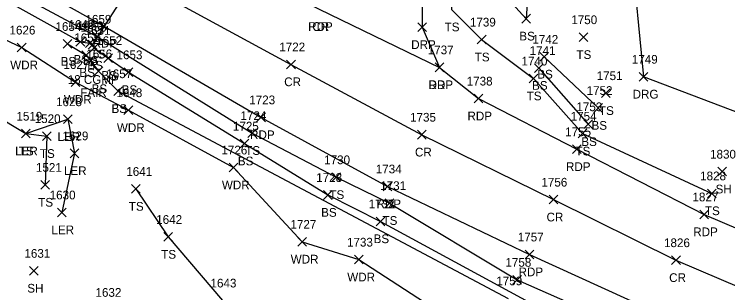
# Model space of a CAD drawing. Extents: x 1586965 to 1590952, y 716317 to 720029.
# Drawn here: x 1587975.1 to 1588139.1, y 719679.3 to 719743.2 of the extents above; entities that cross this region are included whole.
import ezdxf

# ---------------------------------------------------------------- set-up
doc = ezdxf.new("R2010")
doc.units = 0
for name, color, linetype in [('D_A', 7, 'Continuous'), ('D_C', 7, 'Continuous'), ('D_I', 7, 'Continuous'), ('D_TIC', 7, 'Continuous'), ('DCP', 7, 'Continuous'), ('L_A', 7, 'Continuous'), ('L_I', 7, 'Continuous'), ('L_TIC', 7, 'Continuous'), ('LARO', 7, 'Continuous'), ('LAWA', 7, 'Continuous'), ('LELB', 7, 'Continuous'), ('P_A', 7, 'Continuous'), ('P_I', 7, 'Continuous'), ('P_TIC', 7, 'Continuous'), ('PET', 7, 'Continuous'), ('PRC', 7, 'Continuous'), ('R_A', 7, 'Continuous'), ('R_I', 7, 'Continuous'), ('R_TIC', 7, 'Continuous'), ('RDG', 7, 'Continuous'), ('RDP', 7, 'Continuous')]:
    doc.layers.add(name, color=color, linetype=linetype)

msp = doc.modelspace()

# ---------------------------------------------------------------- linework, layer by layer
at = {"layer": 'D_TIC'}
for points in [[(1587992.11, 719735.22), (1587994.11, 719737.22)], [(1587994.11, 719735.22), (1587992.11, 719737.22)]]:
    msp.add_lwpolyline(points, dxfattribs=at)
at = {"layer": 'DCP'}
msp.add_lwpolyline([(1587993.11, 719736.22), (1588025.22, 719785.95)], dxfattribs=at)
at = {"layer": 'L_TIC'}
for points in [[(1588091.75, 719741.19), (1588093.75, 719743.19)], [(1588093.75, 719741.19), (1588091.75, 719743.19)], [(1587993.24, 719737.05), (1587995.24, 719739.05)], [(1587995.24, 719737.05), (1587993.24, 719739.05)], [(1588104.92, 719736.94), (1588106.92, 719738.94)], [(1588106.92, 719736.94), (1588104.92, 719738.94)], [(1587986.33, 719735.39), (1587988.33, 719737.39)], [(1587988.33, 719735.39), (1587986.33, 719737.39)], [(1587989.31, 719735.86), (1587991.31, 719737.86)], [(1587991.31, 719735.86), (1587989.31, 719737.86)], [(1587991.49, 719735.59), (1587993.49, 719737.59)], [(1587993.49, 719735.59), (1587991.49, 719737.59)], [(1588081.54, 719736.39), (1588083.54, 719738.39)], [(1588083.54, 719736.39), (1588081.54, 719738.39)], [(1587975.83, 719734.56), (1587977.83, 719736.56)], [(1587977.83, 719734.56), (1587975.83, 719736.56)], [(1587992.47, 719734.49), (1587994.47, 719736.49)], [(1587994.47, 719734.49), (1587992.47, 719736.49)], [(1587990.65, 719732.83), (1587992.65, 719734.83)], [(1587992.65, 719732.83), (1587990.65, 719734.83)], [(1587995.7, 719732.15), (1587997.7, 719734.15)], [(1587997.7, 719732.15), (1587995.7, 719734.15)], [(1588095.88, 719732.44), (1588097.88, 719734.44)], [(1588097.88, 719732.44), (1588095.88, 719734.44)], [(1587993.47, 719729.11), (1587995.47, 719731.11)], [(1587995.47, 719729.11), (1587993.47, 719731.11)], [(1588000.37, 719728.89), (1588002.37, 719730.89)], [(1588002.37, 719728.89), (1588000.37, 719730.89)], [(1588094.69, 719729.86), (1588096.69, 719731.86)], [(1588096.69, 719729.86), (1588094.69, 719731.86)], [(1588093.48, 719727.45), (1588095.48, 719729.45)], [(1588095.48, 719727.45), (1588093.48, 719729.45)], [(1587988.17, 719726.65), (1587990.17, 719728.65)], [(1587990.17, 719726.65), (1587988.17, 719728.65)], [(1587998.02, 719724.54), (1588000.02, 719726.54)], [(1588000.02, 719724.54), (1587998.02, 719726.54)], [(1588110.09, 719724.09), (1588112.09, 719726.09)], [(1588112.09, 719724.09), (1588110.09, 719726.09)], [(1588108.35, 719720.69), (1588110.35, 719722.69)], [(1588110.35, 719720.69), (1588108.35, 719722.69)], [(1588000.34, 719720.18), (1588002.34, 719722.18)], [(1588002.34, 719720.18), (1588000.34, 719722.18)], [(1587986.47, 719718.11), (1587988.47, 719720.11)], [(1587988.47, 719718.11), (1587986.47, 719720.11)], [(1588106.01, 719716.96), (1588108.01, 719718.96)], [(1588108.01, 719716.96), (1588106.01, 719718.96)], [(1587976.76, 719714.8), (1587978.76, 719716.8)], [(1587978.76, 719714.8), (1587976.76, 719716.8)], [(1587976.76, 719714.8), (1587978.76, 719716.8)], [(1587978.76, 719714.8), (1587976.76, 719716.8)], [(1587981.6, 719714.23), (1587983.6, 719716.23)], [(1587983.6, 719714.23), (1587981.6, 719716.23)], [(1588028.81, 719714.93), (1588030.81, 719716.93)], [(1588030.81, 719714.93), (1588028.81, 719716.93)], [(1588104.69, 719714.8), (1588106.69, 719716.8)], [(1588106.69, 719714.8), (1588104.69, 719716.8)], [(1588027.07, 719712.52), (1588029.07, 719714.52)], [(1588029.07, 719712.52), (1588027.07, 719714.52)], [(1587987.96, 719710.28), (1587989.96, 719712.28)], [(1587989.96, 719710.28), (1587987.96, 719712.28)], [(1588024.48, 719707.03), (1588026.48, 719709.03)], [(1588026.48, 719707.03), (1588024.48, 719709.03)], [(1588136.81, 719706.08), (1588138.81, 719708.08)], [(1588138.81, 719706.08), (1588136.81, 719708.08)], [(1588048.13, 719704.79), (1588050.13, 719706.79)], [(1588050.13, 719704.79), (1588048.13, 719706.79)], [(1587981.22, 719703.04), (1587983.22, 719705.04)], [(1587983.22, 719703.04), (1587981.22, 719705.04)], [(1588002.04, 719702.11), (1588004.04, 719704.11)], [(1588004.04, 719702.11), (1588002.04, 719704.11)], [(1588046.21, 719700.72), (1588048.21, 719702.72)], [(1588048.21, 719700.72), (1588046.21, 719702.72)], [(1588134.44, 719701.09), (1588136.44, 719703.09)], [(1588136.44, 719701.09), (1588134.44, 719703.09)], [(1588060.35, 719698.86), (1588062.35, 719700.86)], [(1588062.35, 719698.86), (1588060.35, 719700.86)], [(1587985.09, 719696.71), (1587987.09, 719698.71)], [(1587987.09, 719696.71), (1587985.09, 719698.71)], [(1588058.27, 719694.66), (1588060.27, 719696.66)], [(1588060.27, 719694.66), (1588058.27, 719696.66)], [(1588009.49, 719691.09), (1588011.49, 719693.09)], [(1588011.49, 719691.09), (1588009.49, 719693.09)], [(1588040.3, 719689.98), (1588042.3, 719691.98)], [(1588042.3, 719689.98), (1588040.3, 719691.98)], [(1588053.29, 719685.88), (1588055.29, 719687.88)], [(1588055.29, 719685.88), (1588053.29, 719687.88)], [(1587978.63, 719683.31), (1587980.63, 719685.31)], [(1587980.63, 719683.31), (1587978.63, 719685.31)], [(1588089.7, 719681.25), (1588091.7, 719683.25)], [(1588091.7, 719681.25), (1588089.7, 719683.25)]]:
    msp.add_lwpolyline(points, dxfattribs=at)
at = {"layer": 'LARO'}
msp.add_lwpolyline([(1587977.76, 719715.8), (1587987.47, 719719.11), (1587988.96, 719711.28), (1587986.09, 719697.71)], dxfattribs=at)
at = {"layer": 'LAWA'}
msp.add_lwpolyline([(1587792.66, 719819.32), (1587813.67, 719812.11), (1587842.94, 719804.53), (1587864.87, 719797.45), (1587880.05, 719791.05), (1587889.14, 719781.4), (1587900.01, 719769.71), (1587919.42, 719757.56), (1587933.18, 719752.9), (1587956.11, 719747.4), (1587965.59, 719740.84), (1587976.83, 719735.56), (1587989.17, 719727.65), (1588001.34, 719721.18), (1588025.48, 719708.03), (1588041.3, 719690.98), (1588054.29, 719686.88), (1588082.98, 719668.28), (1588093.79, 719656.56), (1588121.25, 719657.28), (1588128.24, 719644.6), (1588131.95, 719613.69), (1588124.34, 719595.05)], dxfattribs=at)
at = {"layer": 'LELB'}
for points in [[(1588105.6, 719837.99), (1588091.13, 719809.31), (1588078.49, 719778.05), (1588074.83, 719757.06), (1588075.62, 719744.29), (1588082.54, 719737.39), (1588094.48, 719728.45), (1588105.69, 719715.8), (1588135.44, 719702.09)], [(1588105.6, 719837.99), (1588091.13, 719809.31), (1588078.49, 719778.05), (1588074.83, 719757.06), (1588075.62, 719744.29), (1588082.54, 719737.39), (1588094.48, 719728.45), (1588105.69, 719715.8), (1588135.44, 719702.09)], [(1587769.54, 719828.25), (1587817.81, 719818.92), (1587845.39, 719810.87), (1587866.59, 719802.16), (1587894.5, 719791.41), (1587924.64, 719774.45), (1587960.66, 719756.07), (1587994.24, 719738.05), (1588029.81, 719715.93), (1588049.13, 719705.79), (1588061.35, 719699.86), (1588090.7, 719682.25), (1588125.12, 719667.08), (1588163.84, 719653.66), (1588168.64, 719652.01), (1588170.5, 719647.84), (1588169.34, 719638.56), (1588158.94, 719617.68), (1588144.69, 719590.38)], [(1587769.54, 719828.25), (1587817.81, 719818.92), (1587845.39, 719810.87), (1587866.59, 719802.16), (1587894.5, 719791.41), (1587924.64, 719774.45), (1587960.66, 719756.07), (1587994.24, 719738.05), (1588029.81, 719715.93), (1588049.13, 719705.79), (1588061.35, 719699.86), (1588090.7, 719682.25), (1588125.12, 719667.08), (1588163.84, 719653.66), (1588168.64, 719652.01), (1588170.5, 719647.84), (1588169.34, 719638.56), (1588158.94, 719617.68), (1588144.69, 719590.38)], [(1588123.41, 719820.91), (1588113.55, 719802.78), (1588098.59, 719770.05), (1588093.49, 719753.16), (1588092.75, 719742.19), (1588084.04, 719751.79)], [(1588123.41, 719820.91), (1588113.55, 719802.78), (1588098.59, 719770.05), (1588093.49, 719753.16), (1588092.75, 719742.19), (1588084.04, 719751.79)], [(1587893.61, 719788.22), (1587923.32, 719772.46), (1587959.45, 719753.99), (1587990.31, 719736.86), (1587992.49, 719736.59), (1587993.47, 719735.49), (1587996.7, 719733.15), (1588001.37, 719729.89), (1588028.07, 719713.52), (1588047.21, 719701.72), (1588059.27, 719695.66), (1588101.54, 719672.79), (1588123.97, 719663.55), (1588153.31, 719655.21), (1588167.62, 719650.14)], [(1587893.61, 719788.22), (1587923.32, 719772.46), (1587959.45, 719753.99), (1587990.31, 719736.86), (1587992.49, 719736.59), (1587993.47, 719735.49), (1587996.7, 719733.15), (1588001.37, 719729.89), (1588028.07, 719713.52), (1588047.21, 719701.72), (1588059.27, 719695.66), (1588101.54, 719672.79), (1588123.97, 719663.55), (1588153.31, 719655.21), (1588167.62, 719650.14)], [(1587987.33, 719736.39), (1587991.65, 719733.83), (1587994.47, 719730.11), (1587999.02, 719725.54), (1588088.6, 719677.99)], [(1587987.33, 719736.39), (1587991.65, 719733.83), (1587994.47, 719730.11), (1587999.02, 719725.54), (1588088.6, 719677.99)], [(1588096.88, 719733.44), (1588109.35, 719721.69)], [(1588096.88, 719733.44), (1588109.35, 719721.69)], [(1588095.69, 719730.86), (1588107.01, 719717.96)], [(1588095.69, 719730.86), (1588107.01, 719717.96)], [(1587929.67, 719702.87), (1587946.9, 719706.83), (1587961.12, 719718.46), (1587970.17, 719720.37), (1587977.76, 719715.8), (1587982.6, 719715.23), (1587982.22, 719704.04)], [(1587929.67, 719702.87), (1587946.9, 719706.83), (1587961.12, 719718.46), (1587970.17, 719720.37), (1587977.76, 719715.8), (1587982.6, 719715.23), (1587982.22, 719704.04)], [(1588003.04, 719703.11), (1588010.49, 719692.09), (1588022.97, 719677.49), (1588035.84, 719670.97), (1588033.76, 719652.19), (1588022.75, 719659.05), (1588021.96, 719651.07)], [(1588003.04, 719703.11), (1588010.49, 719692.09), (1588022.97, 719677.49), (1588035.84, 719670.97), (1588033.76, 719652.19), (1588022.75, 719659.05), (1588021.96, 719651.07)]]:
    msp.add_lwpolyline(points, dxfattribs=at)
at = {"layer": 'P_TIC'}
for points in [[(1587994.65, 719739.56), (1587996.65, 719741.56)], [(1587996.65, 719739.56), (1587994.65, 719741.56)], [(1588037.72, 719730.7), (1588039.72, 719732.7)], [(1588039.72, 719730.7), (1588037.72, 719732.7)], [(1588071.84, 719730.02), (1588073.84, 719732.02)], [(1588073.84, 719730.02), (1588071.84, 719732.02)], [(1588080.8, 719722.85), (1588082.8, 719724.85)], [(1588082.8, 719722.85), (1588080.8, 719724.85)], [(1588030.83, 719718.54), (1588032.83, 719720.54)], [(1588032.83, 719718.54), (1588030.83, 719720.54)], [(1588067.79, 719714.56), (1588069.79, 719716.56)], [(1588069.79, 719714.56), (1588067.79, 719716.56)], [(1588103.43, 719711.22), (1588105.43, 719713.22)], [(1588105.43, 719711.22), (1588103.43, 719713.22)], [(1588059.89, 719702.68), (1588061.89, 719704.68)], [(1588061.89, 719702.68), (1588059.89, 719704.68)], [(1588098.02, 719699.65), (1588100.02, 719701.65)], [(1588100.02, 719699.65), (1588098.02, 719701.65)], [(1588132.68, 719696.26), (1588134.68, 719698.26)], [(1588134.68, 719696.26), (1588132.68, 719698.26)], [(1588092.53, 719687.06), (1588094.53, 719689.06)], [(1588094.53, 719687.06), (1588092.53, 719689.06)], [(1588126.2, 719685.75), (1588128.2, 719687.75)], [(1588128.2, 719685.75), (1588126.2, 719687.75)]]:
    msp.add_lwpolyline(points, dxfattribs=at)
at = {"layer": 'PET'}
for points in [[(1587795.98, 719858.74), (1587820.3, 719853.13), (1587857.37, 719841.42), (1587877.69, 719833.83), (1587907.04, 719819.84), (1587939.32, 719802.03), (1587973.69, 719783.16), (1588008.21, 719763.34), (1588019.61, 719757.58), (1588045.18, 719744.38), (1588072.84, 719731.02), (1588081.8, 719723.85), (1588104.43, 719712.22), (1588133.68, 719697.26), (1588170.87, 719681.39), (1588198.42, 719670.99), (1588228.28, 719659.25)], [(1587769.59, 719834.05), (1587819.16, 719826.14), (1587848.36, 719816.77), (1587868.73, 719807.9), (1587895.82, 719795.75), (1587926.99, 719779.02), (1587962.24, 719759.15), (1587995.65, 719740.56), (1588031.83, 719719.54), (1588060.89, 719703.68), (1588093.53, 719688.06), (1588127.35, 719672.7), (1588165.1, 719657.02), (1588195.68, 719645.12), (1588212.38, 719637.86), (1588219.86, 719635.29)]]:
    msp.add_lwpolyline(points, dxfattribs=at)
at = {"layer": 'PRC'}
msp.add_lwpolyline([(1587770.57, 719846.88), (1587822.37, 719838.71), (1587852.49, 719828.95), (1587873.58, 719820.04), (1587901.35, 719807.55), (1587933.49, 719790.19), (1587967.95, 719771.53), (1588001.84, 719751.71), (1588038.72, 719731.7), (1588068.79, 719715.56), (1588099.02, 719700.65), (1588127.2, 719686.75), (1588167.73, 719669.46), (1588194.58, 719658.84), (1588224.51, 719647.27)], dxfattribs=at)
msp.add_lwpolyline([(1587770.57, 719846.88), (1587822.37, 719838.71), (1587852.49, 719828.95), (1587873.58, 719820.04), (1587901.35, 719807.55), (1587933.49, 719790.19), (1587967.95, 719771.53), (1588001.84, 719751.71), (1588038.72, 719731.7), (1588068.79, 719715.56), (1588099.02, 719700.65), (1588127.2, 719686.75), (1588167.73, 719669.46), (1588194.58, 719658.84), (1588224.51, 719647.27)], dxfattribs=at)
at = {"layer": 'R_TIC'}
for points in [[(1588067.87, 719739.24), (1588069.87, 719741.24)], [(1588069.87, 719739.24), (1588067.87, 719741.24)], [(1588071.84, 719730.02), (1588073.84, 719732.02)], [(1588073.84, 719730.02), (1588071.84, 719732.02)], [(1588118.75, 719727.86), (1588120.75, 719729.86)], [(1588120.75, 719727.86), (1588118.75, 719729.86)]]:
    msp.add_lwpolyline(points, dxfattribs=at)
at = {"layer": 'RDG'}
for points in [[(1588132.37, 719800.17), (1588122.59, 719770.23), (1588116.89, 719757.98), (1588119.75, 719728.86)], [(1588144.2, 719719.61), (1588119.75, 719728.86)]]:
    msp.add_lwpolyline(points, dxfattribs=at)
at = {"layer": 'RDP'}
msp.add_lwpolyline([(1588103, 719839.85), (1588088.76, 719810.16), (1588075.61, 719779.11), (1588068.76, 719760.89), (1588068.87, 719740.24), (1588072.84, 719731.02)], dxfattribs=at)

# ---------------------------------------------------------------- texts
at = {"layer": 'D_A'}
msp.add_text('P', height=2, dxfattribs=at).set_placement((1587992.49, 719731.22))
at = {"layer": 'D_C'}
for s, p in [('18 CGMP', (1587987.41, 719727.22)), ('FAIR', (1587990.29, 719724.22))]:
    msp.add_text(s, height=2, dxfattribs=at).set_placement(p)
at = {"layer": 'D_I'}
msp.add_text('1658', height=2, dxfattribs=at).set_placement((1587990.37, 719739.22))
at = {"layer": 'L_A'}
for s, p in [('TS', (1588074.03, 719739.29)), ('BS', (1588091.19, 719737.19)), ('BS', (1587988.75, 719731.86)), ('TS', (1587992.65, 719733.05)), ('TS', (1588080.95, 719732.39)), ('TS', (1588104.33, 719732.94)), ('WDR', (1587974.19, 719730.56)), ('BS', (1587985.78, 719731.39)), ('BS', (1587990.93, 719731.59)), ('BS', (1587991.91, 719730.49)), ('BS', (1587990.09, 719728.83)), ('BS', (1587995.14, 719728.15)), ('BS', (1588095.32, 719728.44)), ('BS', (1588094.13, 719725.86)), ('BS', (1587992.91, 719725.11)), ('BS', (1587999.81, 719724.89)), ('WDR', (1587986.53, 719722.65)), ('TS', (1588092.89, 719723.45)), ('BS', (1587997.47, 719720.54)), ('TS', (1588109.5, 719720.09)), ('WDR', (1587998.71, 719716.18)), ('BS', (1588107.79, 719716.69)), ('LER', (1587985.06, 719714.11)), ('BS', (1588105.45, 719712.96)), ('LER', (1587975.34, 719710.8)), ('TS', (1587976.17, 719710.8)), ('TS', (1588028.22, 719710.93)), ('TS', (1588104.1, 719710.8)), ('TS', (1587981.01, 719710.23)), ('BS', (1588026.51, 719708.52)), ('LER', (1587986.54, 719706.28)), ('WDR', (1588022.84, 719703.03)), ('TS', (1588047.54, 719700.79)), ('SH', (1588136.3, 719702.08)), ('TS', (1587980.63, 719699.04)), ('TS', (1588001.45, 719698.11)), ('BS', (1588045.65, 719696.72)), ('TS', (1588133.85, 719697.09)), ('TS', (1588059.76, 719694.86)), ('LER', (1587983.67, 719692.71)), ('BS', (1588057.71, 719690.66)), ('TS', (1588008.9, 719687.09)), ('WDR', (1588038.66, 719685.98)), ('WDR', (1588051.65, 719681.88)), ('SH', (1587978.12, 719679.31))]:
    msp.add_text(s, height=2, dxfattribs=at).set_placement(p)
at = {"layer": 'L_I'}
for s, p in [('1659', (1587991.49, 719741.05)), ('1739', (1588079.84, 719740.39)), ('1750', (1588103.14, 719740.94)), ('1626', (1587974.03, 719738.56)), ('1654', (1587984.59, 719739.39)), ('1649', (1587987.56, 719739.86)), ('1650', (1587989.66, 719739.59)), ('1651', (1587991.3, 719738.49)), ('1655', (1587988.91, 719736.83)), ('1652', (1587993.96, 719736.15)), ('1742', (1588094.19, 719736.44)), ('1741', (1588093.56, 719733.86)), ('1656', (1587991.68, 719733.11)), ('1653', (1587998.63, 719732.89)), ('1627', (1587986.43, 719730.65)), ('1740', (1588091.7, 719731.45)), ('1657', (1587996.28, 719728.54)), ('1751', (1588108.97, 719728.09)), ('1648', (1587998.6, 719724.18)), ('1752', (1588106.66, 719724.69)), ('1628', (1587984.73, 719722.11)), ('1753', (1588104.31, 719720.96)), ('1519', (1587975.63, 719718.8)), ('1519', (1587975.63, 719718.8)), ('1724', (1588027.12, 719718.93)), ('1754', (1588103, 719718.8)), ('1520', (1587979.82, 719718.23)), ('1725', (1588025.37, 719716.52)), ('1629', (1587986.21, 719714.28)), ('1726', (1588022.73, 719711.03)), ('1830', (1588135.03, 719710.08)), ('1730', (1588046.35, 719708.79)), ('1521', (1587980.1, 719707.04)), ('1641', (1588000.87, 719706.11)), ('1728', (1588044.52, 719704.72)), ('1828', (1588132.75, 719705.09)), ('1731', (1588059.23, 719702.86)), ('1630', (1587983.26, 719700.71)), ('1732', (1588056.57, 719698.66)), ('1642', (1588007.75, 719695.09)), ('1727', (1588038.6, 719693.98)), ('1733', (1588051.59, 719689.88)), ('1631', (1587977.46, 719687.31)), ('1758', (1588088, 719685.25)), ('1759', (1588085.9, 719680.99)), ('1643', (1588020.23, 719680.49)), ('1632', (1587993.79, 719678.35))]:
    msp.add_text(s, height=2, dxfattribs=at).set_placement(p)
at = {"layer": 'P_A'}
for s, p in [('RDP', (1588042.67, 719739.38)), ('CR', (1588043.62, 719739.38)), ('RDP', (1587993.13, 719735.56)), ('CR', (1588037.16, 719726.7)), ('RDP', (1588070.33, 719726.02)), ('RDP', (1588079.28, 719718.85)), ('RDP', (1588029.32, 719714.54)), ('CR', (1588067.22, 719710.56)), ('RDP', (1588101.92, 719707.22)), ('RDP', (1588058.38, 719698.68)), ('CR', (1588097.45, 719695.65)), ('RDP', (1588131.17, 719692.26)), ('RDP', (1588091.02, 719683.06)), ('CR', (1588125.63, 719681.75))]:
    msp.add_text(s, height=2, dxfattribs=at).set_placement(p)
at = {"layer": 'P_I'}
for s, p in [('1722', (1588036.03, 719734.7)), ('1737', (1588070.15, 719734.02)), ('1738', (1588079.1, 719726.85)), ('1723', (1588029.13, 719722.54)), ('1735', (1588066.09, 719718.56)), ('1755', (1588101.74, 719715.22)), ('1734', (1588058.2, 719706.68)), ('1756', (1588096.27, 719703.65)), ('1827', (1588130.99, 719700.26)), ('1757', (1588090.84, 719691.06)), ('1826', (1588124.45, 719689.75))]:
    msp.add_text(s, height=2, dxfattribs=at).set_placement(p)
at = {"layer": 'R_A'}
for s, p in [('DRP', (1588066.35, 719735.24)), ('DRP', (1588070.33, 719726.02)), ('DRG', (1588117.23, 719723.86))]:
    msp.add_text(s, height=2, dxfattribs=at).set_placement(p)
at = {"layer": 'R_I'}
for s, p in [('1737', (1588070.15, 719734.02)), ('1749', (1588117.05, 719731.86))]:
    msp.add_text(s, height=2, dxfattribs=at).set_placement(p)

doc.saveas('drawing.dxf')
